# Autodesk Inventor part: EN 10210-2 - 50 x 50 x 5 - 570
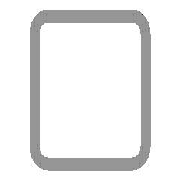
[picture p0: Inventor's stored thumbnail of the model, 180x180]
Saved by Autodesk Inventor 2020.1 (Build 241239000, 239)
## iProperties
IsCustomPart: 1
Created: 2019-01
Part Number: EN 10210-2 - 50 x 50 x 5 - 570
Material: Stahl, weich
Description: Rohrleitung
Document SubType Name: Modeling
Standard: DIN
Designer: lutzd
Standard Revision: 2006-07
Standards Organization: DIN
Language: de-DE
Size Designation: 50 x 50 x 5
Categories: <MemberInstance><Categories><Category DisplayName="Profile" InternalName="089c4875-fa83-4c05-b084-43b9cc11f5ed" Mnemonic="GRDR"><CategoryParameter DisplayName="
Stock Number: 50 x 50 x 5
Mass: 3907.02 g
Surface Area: 1947.14 cm^2
Volume: 497.71 cm^3
Density: 7.85 g/cm^3
Appearance: Halbpoliert
_CCFamilyMember: 16
_CCFamilyDisplayName: DIN EN 10210-2 (USAS B17.1 quadratisch) - Rohrleitung — In Klammern angegebene Größen wurden aufgehoben
_FrameMemberDoc: Frame Member File
_Version: 15.0.0
_GetPNFromCC: 1
G_L: 570,000 mm
G_W: 50,000 mm
G_H: 50,000 mm
Dimensions: 50x50x570 mm
Mass: 3,907 kg
DocNumber: ADSK-014148
Folder: .
Title: Profil-Bauteil
Author: lutzd
Revision Number: -
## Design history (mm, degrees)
node "Startebene"
node "Endebene"
sketch "Skizze"
  geometry: L1 (-25, -17.5)-(-25, 17.5); L2 (-17.5, 25)-(17.5, 25); L3 (25, 17.5)-(25, -17.5); L4 (17.5, -25)-(-17.5, -25); L5 (-15, 20)-(15, 20); L6 (20, 15)-(20, -15); L7 (15, -20)-(-15, -20); L8 (-20, -15)-(-20, 15); L9 (0, 37.175)-(0, -37.175) reference; L10 (-37.175, 0)-(37.175, 0) reference; A1 r 7.5 centre (-17.5, -17.5) between (-25, -17.5) and (-17.5, -25); A2 r 7.5 centre (-17.5, 17.5) between (-17.5, 25) and (-25, 17.5); A3 r 7.5 centre (17.5, 17.5) between (25, 17.5) and (17.5, 25); A4 r 7.5 centre (17.5, -17.5) between (17.5, -25) and (25, -17.5); A5 r 5 centre (-15, -15) between (-20, -15) and (-15, -20); A6 r 5 centre (-15, 15) between (-15, 20) and (-20, 15); A7 r 5 centre (15, 15) between (20, 15) and (15, 20); A8 r 5 centre (15, -15) between (15, -20) and (20, -15)
  constraints: 16 end point, 16 point on circle, 16 tangent, 8 centre point, 6 equal radius, 4 parallel, 2 perpendicular, 2 other
  dimensions: "d7" = 7.5 radius of A1 (= G_IR); "d10" = 50 distance between parallel lines of L2 L4 (= G_H); "d11" = 50 distance between parallel lines of L1 L3 (= G_W); "d12" = 5 distance between parallel lines of L3 L6 (= G_T); "d15" = 25 distance between parallel lines of L2 L10 (= 0.5 x d10); "d16" = 25 distance between parallel lines of L9 L3 (= 0.5 x d11); "d19" = 5 radius of A5 (= G_T); "d20" = 5 distance between parallel lines of L4 L7 (= G_T)
extrude "Körper" new body sketch "Skizze" stored distance "d3" = 570 (= G_L); taper "d4" = 0 deg
node "Driven Length"
  sketch "Sketch3"
    geometry: L1 (0, 0)-(10, 0) reference
    constraints: 2 end point, 1 horizontal
  workplane "Work Plane3"
  sketch "Sketch4"
    geometry: L1 (-2, 0)-(12, 0) reference; L2 (-2, 570)-(12, 570) reference
    dimensions: "d18" = 570 distance between parallel lines of L1 L2 (derived)
workplane "Arbeitsebene4"
feature "Trennen1"
body "Solid1"
other parameters: "G_W" = 50 [user parameter; used in 1 equation term], "G_H" = 50 [user parameter; used in 1 equation term], "G_T" = 5 [user parameter; used in 3 equation terms], "G_IR" = 7.5 [user parameter; used in 1 equation term], "G_L" = 570 (= d18) [user parameter; used in 1 equation term], "G_OFFSET_START" = 0 [user parameter; used in 1 equation term], "d13" = 0 (computed from G_OFFSET_START), "d17" = 90 deg
